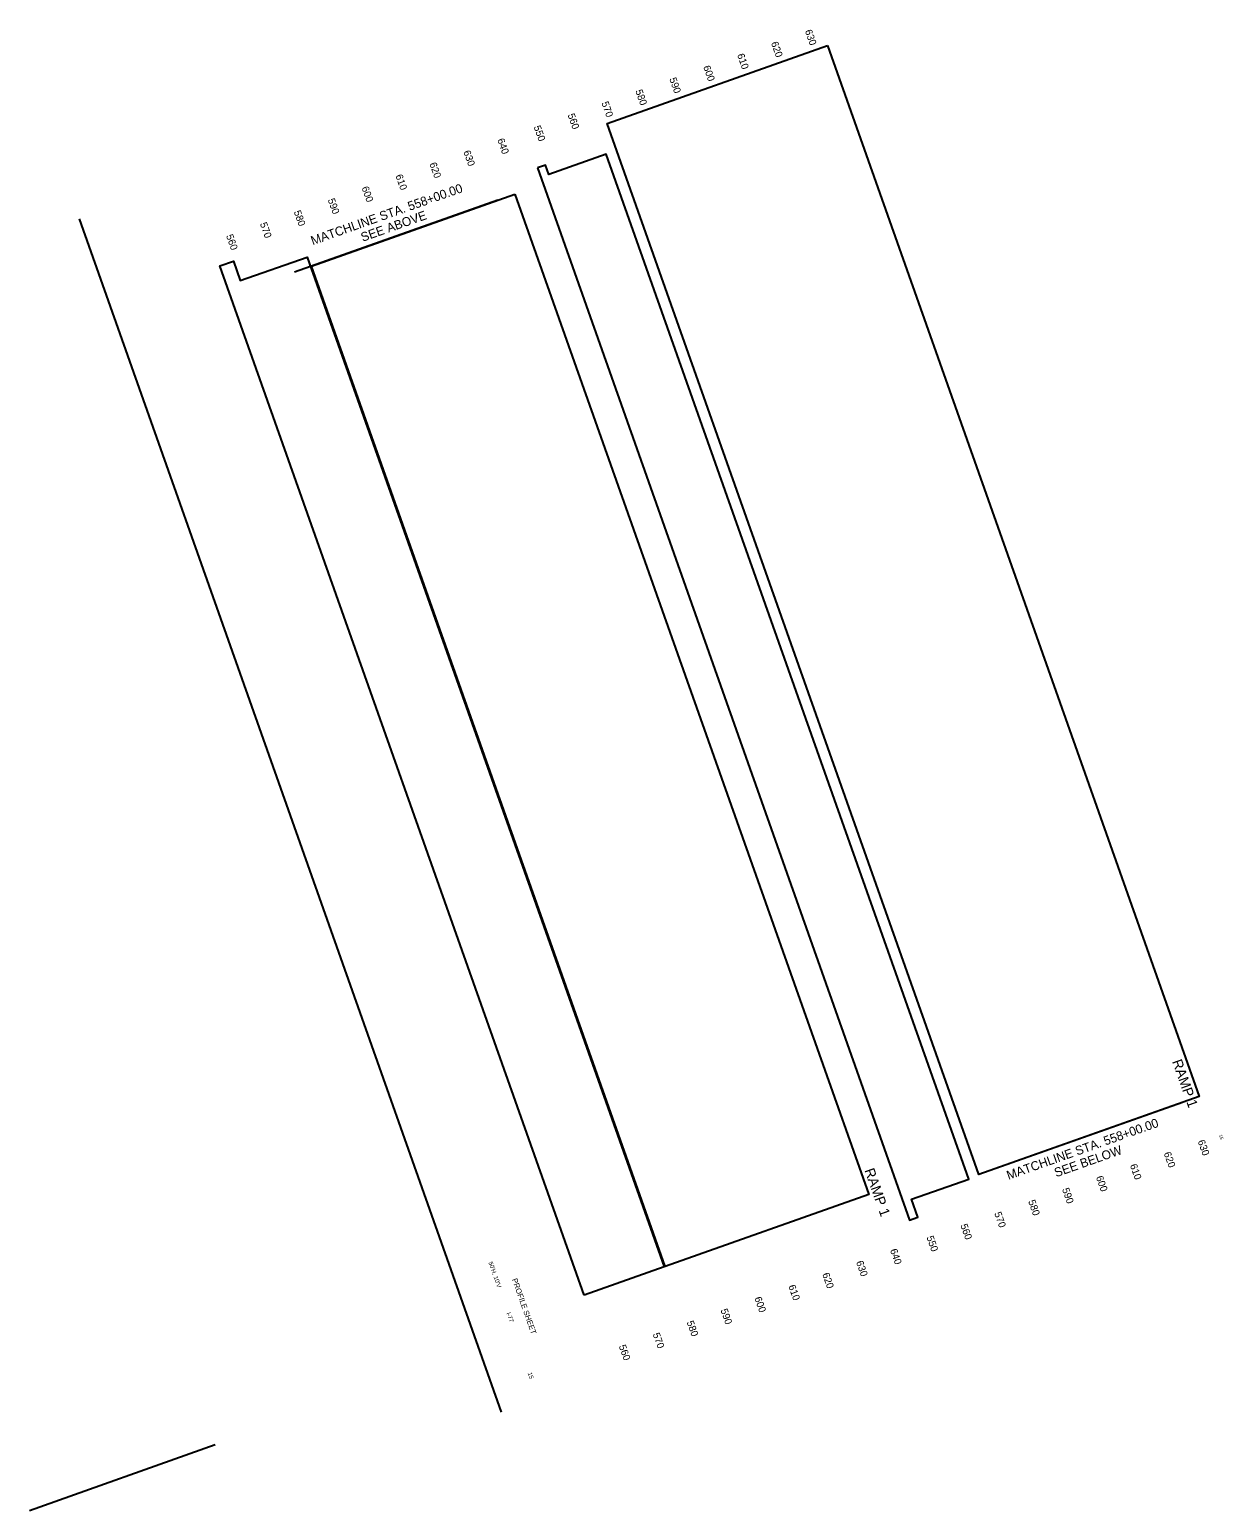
# Model space of a CAD drawing. Extents: x 1990347 to 1992007, y 1125602 to 1127660.
import ezdxf

# ---------------------------------------------------------------- set-up
doc = ezdxf.new("R2010")
doc.units = 0
for name, color, linetype in [('RD_DDB_ElevTX', 7, 'Continuous'), ('RD_DDB_Profile_Lbl', 7, 'Continuous'), ('RD_DDB_Profile_PR', 7, 'Continuous')]:
    doc.layers.add(name, color=color, linetype=linetype)

msp = doc.modelspace()

# ---------------------------------------------------------------- linework, layer by layer
at = {"layer": 'RD_DDB_ElevTX'}
msp.add_line((1990415.9, 1127397.5), (1991002.8, 1125738.3), dxfattribs=at)
at = {"layer": 'RD_DDB_Profile_Lbl'}
msp.add_line((1990347, 1125601.6), (1990605.2, 1125693), dxfattribs=at)
for points in [[(1991456.4, 1127638.2), (1991973.4, 1126177), (1991667, 1126068.6), (1991150, 1127529.8)], [(1991053.1, 1127468.1), (1991570.6, 1126005.3), (1991581.8, 1126009.3), (1991573.1, 1126034.1), (1991652.7, 1126062.2), (1991148.6, 1127487.1), (1991069, 1127458.9), (1991064.4, 1127472.1)], [(1991021.7, 1127431.4), (1991513.7, 1126040.9), (1991230.8, 1125940.8), (1990738.9, 1127331.4)], [(1991117.9, 1125900.8), (1990611.6, 1127331.9), (1990630.3, 1127338.5), (1990639.9, 1127311.4), (1990732.7, 1127344.2), (1991229.3, 1125940.3)]]:
    msp.add_lwpolyline(points, close=True, dxfattribs=at)
at = {"layer": 'RD_DDB_Profile_PR'}
for p, q in [((1990998.2, 1127423.1), (1990715.4, 1127323)), ((1991949.8, 1126168.6), (1991667, 1126068.6))]:
    msp.add_line(p, q, dxfattribs=at)

# ---------------------------------------------------------------- texts
at = {"layer": 'RD_DDB_ElevTX'}
for s, height, p in [('630', 10, (1991424.8, 1127658.5)), ('620', 10, (1991377.7, 1127641.8)), ('610', 10, (1991330.6, 1127625.2)), ('600', 10, (1991283.4, 1127608.5)), ('590', 10, (1991236.3, 1127591.8)), ('570', 10, (1991142, 1127558.5)), ('580', 10, (1991189.1, 1127575.1)), ('560', 10, (1991094.9, 1127541.8)), ('550', 10, (1991047.7, 1127525.1)), ('640', 10, (1990997.1, 1127507.2)), ('620', 10, (1990902.8, 1127473.8)), ('630', 10, (1990949.9, 1127490.5)), ('610', 10, (1990855.6, 1127457.2)), ('600', 10, (1990808.5, 1127440.5)), ('590', 10, (1990761.4, 1127423.8)), ('570', 10, (1990667.1, 1127390.5)), ('580', 10, (1990714.2, 1127407.1)), ('560', 10, (1990620, 1127373.8)), ('RAMP 1', 14, (1991935.4, 1126225.8)), ('630', 10, (1991971, 1126114.8)), ('15', 4.5, (1992000.5, 1126123.3)), ('620', 10, (1991923.8, 1126098.1)), ('RAMP 1', 14, (1991507.6, 1126074.5)), ('610', 10, (1991876.7, 1126081.4)), ('600', 10, (1991829.5, 1126064.8)), ('590', 10, (1991782.4, 1126048.1)), ('570', 10, (1991688.1, 1126014.7)), ('580', 10, (1991735.3, 1126031.4)), ('560', 10, (1991641, 1125998)), ('550', 10, (1991593.9, 1125981.4)), ('640', 10, (1991543.2, 1125963.4)), ("50'H, 10'V", 6, (1990984.9, 1125946.3)), ('620', 10, (1991448.9, 1125930.1)), ('630', 10, (1991496, 1125946.8)), ('PROFILE SHEET', 7.5, (1991017.6, 1125922.7)), ('610', 10, (1991401.8, 1125913.4)), ('600', 10, (1991354.6, 1125896.7)), ('I-77', 6, (1991009.9, 1125875.8)), ('590', 10, (1991307.5, 1125880.1)), ('570', 10, (1991213.2, 1125846.7)), ('580', 10, (1991260.4, 1125863.4)), ('560', 10, (1991166.1, 1125830)), ('15', 6, (1991039.4, 1125792.4))]:
    msp.add_text(s, height=height, rotation=289.482, dxfattribs=at).set_placement(p)
at = {"layer": 'RD_DDB_Profile_PR'}
for s, p in [('MATCHLINE STA. 558+00.00', (1990740.6, 1127360.6)), ('SEE ABOVE', (1990810.1, 1127365.3)), ('MATCHLINE STA. 558+00.00', (1991708.1, 1126061.1)), ('SEE BELOW', (1991774.3, 1126064.7))]:
    msp.add_text(s, height=12.5, rotation=19.482, dxfattribs=at).set_placement(p)

doc.saveas('drawing.dxf')
